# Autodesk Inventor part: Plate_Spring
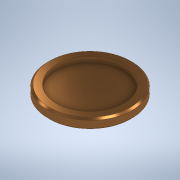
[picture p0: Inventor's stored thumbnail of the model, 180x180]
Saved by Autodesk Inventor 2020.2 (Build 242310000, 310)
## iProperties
Created: 2020-01
Part Number: Plate_Spring
Material: Steel, Carbon
Document SubType Name: Modeling
Designer: thira
Density: 7.85 g/cm^3
Appearance: Semi-Polished
Author: thira
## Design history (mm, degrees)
sketch "Sketch1"
  geometry: C1 r 100 at (0, 0); C2 r 125 at (0, 0); 1 further point
  constraints: 2 centre point, 2 coincident
  dimensions: "d0" = 200 diameter of C1; "d1" = 250 diameter of C2
extrude "Extrusion1" new body sketch "Sketch1" distance "d2" = 30; taper "d3" = 0 deg
extrude "Extrusion2" cut sketch "Sketch1" distance "d4" = 15; taper "d5" = 0 deg
chamfer "Chamfer1" distance "d6" = 5; stored, may be unused: second distance "d7" = 2, angle "d8" = 45 deg
chamfer "Chamfer2" distance "d9" = 5; stored, may be unused: second distance "d10" = 2, angle "d11" = 45 deg
sketch "Sketch2"
  geometry: L1 (78.889, -33.659)-(-75.383, -33.659); L2 (-75.383, -33.659)-(-75.383, 35.763); L3 (-75.383, 35.763)-(78.889, 35.763); L4 (78.889, 35.763)-(78.889, -33.659); 1 further point
  constraints: 2 other
emboss "Emboss1" sketch "Sketch2" dims "d12" = 0.2, "d13" = 0
body "Solid1"
